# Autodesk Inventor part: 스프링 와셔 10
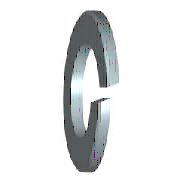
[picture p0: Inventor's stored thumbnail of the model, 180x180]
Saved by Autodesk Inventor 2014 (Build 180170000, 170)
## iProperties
Created: 2012-02
Part Number: 스프링 와셔 10
Material: 강철, 연강
Description: 스프링 잠금 와셔
Document SubType Name: Modeling
Standard: KS B 1324
Designer: mduedu
Standards Organization: KS
Language: ko-KR
Size Designation: 번호 2 - 10
Categories: <MemberInstance><Categories><Category DisplayName="조임쇠" InternalName="e4da775c-781d-43d5-af7c-5136215cf5a6" Mnemonic="FSTN"><Category DisplayName="와셔" InternalN
Density: 1 g/cm^3
Appearance: 강철
IsCustomPart: 1
Author: mduedu
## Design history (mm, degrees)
sketch "스케치1"
  geometry: C1 r 8.8 at (0, 0); C2 r 5.1 at (0, 0); 1 further point
  constraints: 2 centre point, 2 coincident
  dimensions: "d0" = 10.2 diameter of C2 (= SD1); "d1" = 17.6 diameter of C1 (= SD2)
extrude "본체" new body sketch "스케치1" distance "d2" = 2.5 (= SD); taper "d3" = 0 deg
sketch "스케치2"
  geometry: L1 (0, -5.1)-(0, 5.1) reference; L2 (2.5, 8.8)-(2.5, -8.8) reference; L3 (-1.2, 0)-(7.2, 0) reference; L4 (0, -0.5)-(2.5, 0.41); L5 (0, 0.5)-(2.5, 1.41)
  constraints: 4 end point, 4 point on line, 1 parallel
  dimensions: "d4" = 0.5 distance from line of L3 L4.start (= 0.2 x SD); "d5" = 0.5 distance from line of L3 L5.start (= 0.2 x SD); "d6" = 70 deg angle of L2 L4 (= FAWI)
extrude "절단부" cut sketch "스케치2" stored distance "d7" = 2.5 (= SD); taper "d8" = 0 deg
workaxis "Work Axis1"
workplane "Work Plane1"
body "Solid1"
other parameters: "SD1" = 10.2 [user parameter; used in 1 equation term], "SD2" = 17.6 [user parameter; used in 1 equation term], "SD" = 2.5 [user parameter; used in 4 equation terms], "FAWI" = 70 deg [user parameter; used in 1 equation term], "d9" = 0, "d10" = 0, "d11" = 0, "d12" = 0, "SDI" = 3.7 [user parameter]
